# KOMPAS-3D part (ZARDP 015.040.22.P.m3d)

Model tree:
1. Плоскость XY
2. Плоскость ZX
3. Плоскость ZY
4. Ось X
5. Ось Y
6. Ось Z
7. Начало координат
8. Булева операция:5
9. Булева операция:6
10. Булева операция:7
11. Булева операция:8
